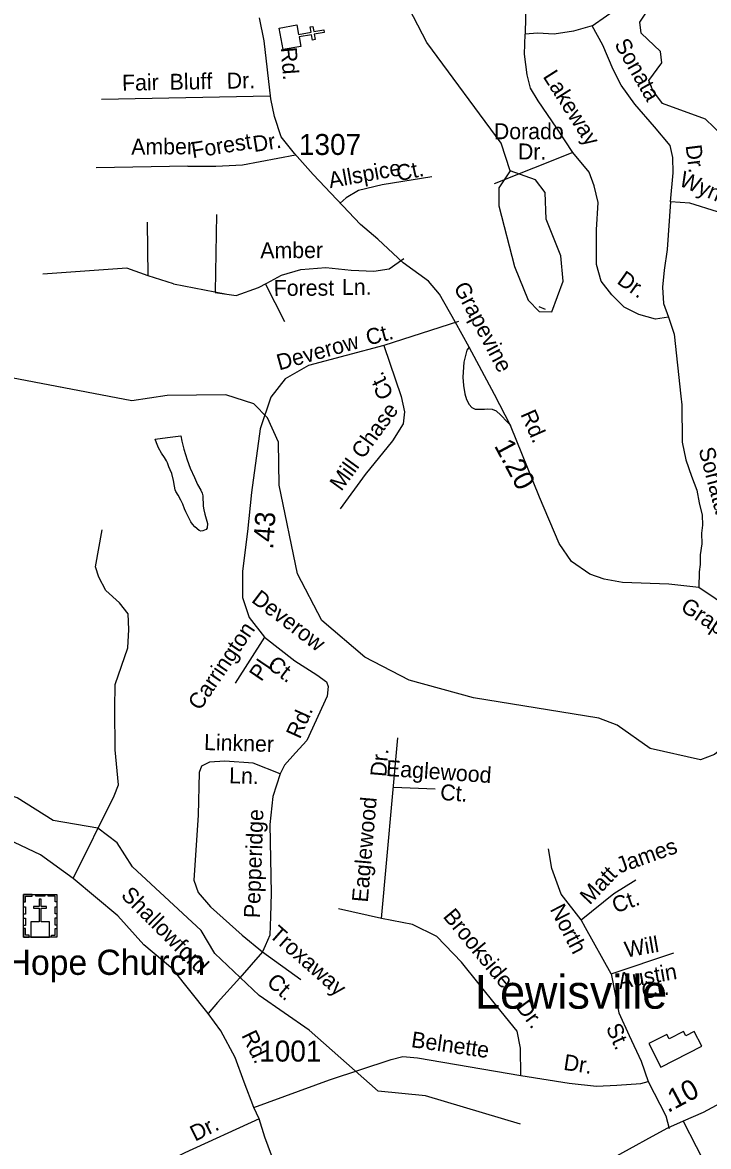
# Model space of a CAD drawing. Extents: x 1547597 to 1699558, y 810033 to 920809.
# Drawn here: x 1576329 to 1580417, y 856928 to 863625 of the extents above; entities that cross this region are included whole.
import ezdxf

# ---------------------------------------------------------------- set-up
doc = ezdxf.new("R2010")
doc.units = 0
for name, color, linetype in [('Exist Civil Demographics Community Label', 7, 'Continuous'), ('Exist Cultural Church CELL', 7, 'Continuous'), ('Exist Cultural Church with Cemetery CELL', 7, 'Continuous'), ('Exist Cultural Church with Cemetery Label', 7, 'Continuous'), ('Exist Cultural Warehouse Building Footprint', 7, 'Continuous'), ('Exist Hydrographic Creek Single Shore', 7, 'Continuous'), ('Exist Hydrographic Misc Water Feature', 7, 'Continuous'), ('Exist Hydrographic Pond Under 1500 Sq Ft', 7, 'Continuous'), ('Exist Road Non-System Type 51', 7, 'Continuous'), ('Exist Road Non-System Type 51 Label', 7, 'Continuous'), ('Exist Road Secondary Mileage Hundredths English Label', 7, 'Continuous'), ('Exist Road Secondary Type 51 Attributed', 7, 'Continuous'), ('Exist Road Secondary Type 51 Label', 7, 'Continuous'), ('Exist Road Secondary Type 51 Number Label', 7, 'Continuous')]:
    doc.layers.add(name, color=color, linetype=linetype)

msp = doc.modelspace()

# ---------------------------------------------------------------- linework, layer by layer
at = {"layer": 'Exist Cultural Church CELL'}
msp.add_lwpolyline([(1577964.1, 863610.7), (1577974.1, 863554.7), (1578049, 863567.9), (1578043.5, 863599.4), (1578059.2, 863602.2), (1578064.8, 863570.7), (1578124, 863581.1), (1578126.8, 863565.3), (1578067.6, 863554.9), (1578073.1, 863523.4), (1578057.4, 863520.6), (1578051.8, 863552.1), (1577976.8, 863538.9), (1577986.7, 863482.1), (1577881.9, 863463.6), (1577859.2, 863592.2)], close=True, dxfattribs=at)
at = {"layer": 'Exist Cultural Church with Cemetery CELL'}
for points in [[(1576335.3, 858430), (1576534.4, 858430), (1576534.4, 858175.3), (1576335.3, 858175.3)], [(1576335.3, 858386.6), (1576346.7, 858386.6), (1576346.7, 858418.8), (1576387.2, 858418.8), (1576387.2, 858430), (1576335.3, 858430)], [(1576378.4, 858175.4), (1576490.6, 858175.4), (1576490.6, 858265.9), (1576439.8, 858265.9), (1576439.8, 858347.4), (1576472.8, 858347.4), (1576472.8, 858358.4), (1576439.8, 858358.4), (1576439.8, 858400.7), (1576428.2, 858400.7), (1576428.2, 858358.4), (1576395.1, 858358.4), (1576395.1, 858347.4), (1576428.2, 858347.4), (1576428.2, 858265.9), (1576378.4, 858265.9)], [(1576409.4, 858429.9), (1576461.2, 858429.9), (1576461.2, 858418.5), (1576409.4, 858418.5)], [(1576534.5, 858386.6), (1576523.1, 858386.6), (1576523.1, 858418.8), (1576482.6, 858418.8), (1576482.6, 858429.9), (1576534.5, 858429.9)], [(1576335.3, 858312.5), (1576335.3, 858355.8), (1576346.7, 858355.8), (1576346.7, 858312.5)], [(1576523.1, 858313.5), (1576523.1, 858356.8), (1576534.5, 858356.8), (1576534.5, 858313.5)], [(1576335.3, 858245.3), (1576335.3, 858288.6), (1576346.7, 858288.6), (1576346.7, 858245.3)], [(1576523, 858247.6), (1576523, 858290.9), (1576534.4, 858290.9), (1576534.4, 858247.6)], [(1576368.4, 858175.4), (1576368.4, 858186.9), (1576346.4, 858186.9), (1576346.4, 858227.3), (1576335.3, 858227.3), (1576335.3, 858175.4)], [(1576501.3, 858175.3), (1576501.3, 858186.8), (1576523.3, 858186.8), (1576523.3, 858227.2), (1576534.4, 858227.2), (1576534.4, 858175.3)]]:
    msp.add_lwpolyline(points, close=True, dxfattribs=at)
at = {"layer": 'Exist Cultural Warehouse Building Footprint'}
msp.add_lwpolyline([(1580131.6, 857401.5), (1580375.9, 857525.1), (1580331.5, 857612.8), (1580280.5, 857586.9), (1580267.7, 857612.4), (1580182.3, 857569.2), (1580169.1, 857595.4), (1580061.2, 857540.7)], close=True, dxfattribs=at)
at = {"layer": 'Exist Hydrographic Creek Single Shore'}
msp.add_lwpolyline([(1579235.5, 862740.9), (1579180.5, 862906), (1578738.5, 863505.9), (1578446.5, 864069.9), (1578303.5, 864529.1), (1578280.5, 864720), (1578145.5, 865139.7), (1578072.5, 865282.3), (1578064.5, 865351.4), (1577879.5, 865795), (1577773.5, 865977.7), (1577495.5, 866301.8), (1577407.4, 866602.3), (1577350.4, 866679), (1577351.5, 866744.6)], dxfattribs=at)
at = {"layer": 'Exist Hydrographic Misc Water Feature'}
for points in [[(1580813.6, 859406.4), (1580663.5, 859393), (1580562.5, 859352.4), (1580452.5, 859262.7), (1580368.5, 859231.5), (1580069.5, 859299.9), (1579871.6, 859438.5), (1579763.5, 859480.1), (1579015.5, 859600.4), (1578633.4, 859706.6), (1578368.5, 859843.3), (1578113.5, 860061.8), (1577967.5, 860340.5), (1577858.5, 860868), (1577853.5, 861124.1), (1577789.5, 861269.9), (1577706.5, 861353.7), (1577540.5, 861406.3), (1577190.5, 861403.5), (1576981.4, 861371.6), (1576125.5, 861533.4), (1575884.5, 861613.8), (1575662.4, 861831.8)], [(1577271.7, 861161.6), (1577277.8, 861129.9), (1577291.2, 861082), (1577311, 861019.8), (1577328.5, 860970.2), (1577353.5, 860913.8), (1577372, 860873.3), (1577391.4, 860838.8), (1577400.4, 860821.1), (1577404.3, 860805.2), (1577405.7, 860744.2), (1577408.7, 860721.5), (1577414.9, 860695.6), (1577427.5, 860654.3), (1577430.6, 860639.3), (1577430.2, 860613.3), (1577424.2, 860604.3), (1577404, 860595.5), (1577391.4, 860594.1), (1577382.3, 860598.4), (1577356.8, 860620.5), (1577342, 860635.9), (1577332.2, 860650.2), (1577318.6, 860678), (1577301.5, 860709.3), (1577295.2, 860727.8), (1577284.7, 860754.6), (1577272.6, 860779.9), (1577256.4, 860808.6), (1577243.4, 860829.8), (1577239.4, 860839.8), (1577234.8, 860861.7), (1577229.6, 860896), (1577218.6, 860937.9), (1577208.8, 860959.9), (1577200.9, 860977.5), (1577193, 861001.9), (1577187.2, 861012.9), (1577175.9, 861033.1), (1577158, 861059.3), (1577140.2, 861090.6), (1577127.3, 861120.8), (1577120.2, 861142.7), (1577193.8, 861152.2), (1577271.7, 861161.6)], [(1579295.5, 857060.4), (1578730.5, 857229.4), (1578447.5, 857258.1), (1578036.5, 857621), (1577738.5, 857827.2), (1577475.5, 858078.8), (1577394.5, 858215.1), (1576983.5, 858594.3), (1576893.5, 858737.4), (1576778.4, 858825), (1576511.5, 858869.8), (1576297.5, 859005.5), (1576164.5, 859050.8), (1576082.5, 859167.4), (1576042.5, 859293), (1576046.5, 859558.8), (1576129.5, 860098.8), (1576126.5, 860433.7), (1576053.5, 860602.6), (1575971.5, 860669.9)]]:
    msp.add_lwpolyline(points, dxfattribs=at)
at = {"layer": 'Exist Hydrographic Pond Under 1500 Sq Ft'}
msp.add_line((1579445, 861916.1), (1579407.6, 861930.3), dxfattribs=at)
for points in [[(1580960.5, 862646.7), (1580860.5, 862642.2), (1580677.5, 862695.2), (1580545.6, 862819.3), (1580497.5, 862954.9), (1580399.5, 863048.7), (1580142.5, 863142.7), (1580085.5, 863219.2), (1580060.5, 863278.9), (1580137.5, 863385.6), (1580129.5, 863451.5), (1580014.5, 863562.2), (1580007.5, 863627.9), (1580101.5, 863770.4)], [(1579235.5, 862740.9), (1579167.5, 862640.4), (1579166.5, 862532.1), (1579260.5, 862172.3), (1579341.5, 861970.5), (1579407.5, 861903.5), (1579482.5, 861902), (1579551.5, 862084.4), (1579537.5, 862235.7), (1579448.5, 862454.2), (1579442.5, 862611.9), (1579385.5, 862688.6), (1579235.5, 862740.9)]]:
    msp.add_lwpolyline(points, dxfattribs=at)
at = {"layer": 'Exist Road Non-System Type 51'}
for p, q in [((1577805.1, 863186.8), (1576799.7, 863166.7)), ((1577639.8, 862777), (1577954.9, 862837.1)), ((1577313.7, 862769.6), (1576768.2, 862759.1)), ((1577313.7, 862769.6), (1577480.4, 862769.6)), ((1577480.4, 862769.6), (1577639.8, 862777)), ((1578472, 862658.4), (1578331.2, 862625)), ((1578768.5, 862706.6), (1578472, 862658.4)), ((1578331.2, 862625), (1578257.1, 862580.5)), ((1578257.1, 862580.5), (1578221.5, 862549.3)), ((1577484.1, 862480.4), (1577476.8, 862019.8)), ((1577077.8, 862116.7), (1577073.2, 862435.6)), ((1578514.3, 862157.8), (1578601.5, 862219.4)), ((1576950.3, 862162.2), (1576449.4, 862125.8)), ((1577077.8, 862116.7), (1576950.3, 862162.2)), ((1577784.3, 862072.5), (1577873.2, 862120.7)), ((1577873.2, 862120.7), (1577988.1, 862154)), ((1577988.1, 862154), (1578136.3, 862165.2)), ((1578136.3, 862165.2), (1578288.2, 862150.3)), ((1578288.2, 862150.3), (1578421.6, 862142.9)), ((1578421.6, 862142.9), (1578514.3, 862157.8)), ((1577228.4, 862068.8), (1577077.8, 862116.7)), ((1577228.4, 862068.8), (1577536.3, 862008.1)), ((1577736.1, 862046.5), (1577784.3, 862072.5)), ((1577891.7, 861842.6), (1577776.9, 862068.5)), ((1577476.7, 862016.8), (1577602.7, 861998.3)), ((1577602.7, 861998.3), (1577736.1, 862046.5)), ((1578467.7, 858286.1), (1578565.1, 859362)), ((1578787.6, 859056.6), (1578539.5, 859066.2)), ((1580265.5, 857078.7), (1580515, 856593.3))]:
    msp.add_line(p, q, dxfattribs=at)
for points in [[(1579356.4, 864184.1), (1579329.4, 863865.4), (1579323.3, 863556.4)], [(1579722.8, 863604.5), (1579894, 863724.7), (1580083.3, 863808.9), (1580194.4, 863863)], [(1579722.8, 863604.5), (1579611.7, 863574.4), (1579497.5, 863556.4), (1579398.4, 863562.4), (1579323.3, 863556.4)], [(1580190.9, 862557.3), (1580206.4, 862729.7), (1580203.4, 862819.9), (1580188.4, 862892.1), (1580095.3, 863003.3), (1579978.1, 863138.6), (1579897, 863252.8), (1579849, 863346), (1579785.9, 863490.3), (1579722.8, 863604.5)], [(1579608.4, 862851.4), (1579512.3, 862995.7), (1579401.2, 863158.1), (1579356.4, 863234.8), (1579335.3, 863312.9), (1579320.3, 863436.2), (1579323.3, 863556.4)], [(1579608.4, 862851.4), (1579140.1, 862663.6)], [(1580179.1, 861869.9), (1580101, 861857.9), (1580001.9, 861884.9), (1579914.8, 861930), (1579839.7, 862002.2), (1579776.6, 862083.3), (1579749.6, 862182.5), (1579749.6, 862390), (1579758.6, 862552.3), (1579734.6, 862653), (1579704.6, 862734.2), (1579608.4, 862851.4)], [(1580190.9, 862557.3), (1580170.1, 862272.7), (1580152.1, 862149.5), (1580143.1, 862047.3), (1580149.1, 861951.1), (1580179.1, 861869.9)], [(1580890.8, 862313.8), (1580800.6, 862367.9), (1580668.5, 862419), (1580470.2, 862497.2), (1580305, 862548.3), (1580190.9, 862557.3)], [(1580179.1, 861869.9), (1580212.1, 861767.7), (1580251.9, 861398.6), (1580257.4, 861346.6), (1580257.4, 861272.7), (1580260.2, 861204.3), (1580260.2, 861124.9), (1580281.9, 861019.8), (1580314.8, 860921.3), (1580347.6, 860839.2), (1580361.2, 860762.5), (1580378.1, 860689), (1580381.3, 860630.9), (1580374.9, 860581.9), (1580377.6, 860519), (1580366.7, 860453.3), (1580366.7, 860395.8), (1580361.2, 860352), (1580358.7, 860258.6)], [(1578927.2, 861843.7), (1578481.5, 861701.2)], [(1578481.5, 861701.2), (1578033.5, 861580.9), (1577893.9, 861503), (1577809.4, 861392.5), (1577744.5, 861204), (1577692.6, 860823.9), (1577669.8, 860593.2), (1577640.6, 860355.3), (1577640.6, 860199.3), (1577679.6, 860079.1), (1577770.5, 859962.1)], [(1578481.5, 861701.2), (1578585.1, 861396.1), (1578604.6, 861305.1), (1578598.1, 861233.6), (1578533.1, 861132.9), (1578370.8, 860931.4), (1578221.4, 860726.7)], [(1578990.2, 861690.5), (1578977.1, 861672.6), (1578958.2, 861600.8), (1578952.9, 861512.8), (1578956, 861462.7), (1578965.4, 861412.7), (1578974.9, 861378.5), (1578990.5, 861348.2), (1579006.2, 861332), (1579026, 861321.6), (1579048.2, 861321.4), (1579082, 861320.9), (1579102.1, 861322.7), (1579128.1, 861322.2), (1579152.1, 861311.9), (1579179.6, 861285.5), (1579217.2, 861244.9), (1579230.9, 861232.6), (1579237.3, 861224.9)], [(1576631.7, 858524.3), (1576875.2, 859018.2), (1576901.2, 859083.2), (1576881.7, 859291.1), (1576878.4, 859538.1), (1576881.7, 859681.1), (1576956.4, 859898.8), (1576962.8, 860007.6), (1576959.6, 860101.8), (1576907.6, 860166.8), (1576826.5, 860241.5), (1576784.3, 860319.5), (1576764.8, 860381.3), (1576803.7, 860602.2)], [(1577770.5, 859962.1), (1577595.2, 859689.2)], [(1577770.5, 859962.1), (1577952.3, 859822.4), (1578082.2, 859737.9), (1578140.6, 859695.7), (1578150.4, 859669.7), (1578143.9, 859611.2), (1578023.8, 859348), (1577956, 859274.3), (1577891, 859199.6), (1577865, 859148.3)], [(1577865, 859148.3), (1577703, 859211.2), (1577534.2, 859224.2), (1577443.3, 859217.7), (1577394.6, 859194.9), (1577381.6, 859155.9), (1577375.1, 858902.5), (1577349.1, 858515.8), (1577375.1, 858441.1), (1577449.8, 858356.6), (1577638.1, 858187.6), (1577758.2, 858086.9)], [(1577865, 859148.3), (1577819.9, 859013), (1577803.7, 858847.3), (1577810.1, 858437.8), (1577806.9, 858298.1), (1577803.7, 858187.6), (1577774.4, 858122.7), (1577758.2, 858086.9)], [(1579658.4, 858279.4), (1579538.3, 858432.2), (1579483.1, 858584.9), (1579463.6, 858701.9)], [(1579658.4, 858279.4), (1579853.2, 858435.4), (1579983.1, 858516.6)], [(1578467.7, 858286.1), (1578211.2, 858344.6)], [(1579298.7, 857351.4), (1579295.5, 857513.8), (1579276, 857614.6), (1579155.9, 857764), (1578944.8, 858027.2), (1578798.7, 858179.9), (1578652.8, 858250.3), (1578467.7, 858286.1)], [(1579836.9, 857956), (1579684.4, 858230.7), (1579658.4, 858279.4)], [(1577758.2, 858086.9), (1577624.5, 857932.5), (1577491.4, 857786.3), (1577435, 857720.7)], [(1577758.2, 858086.9), (1577988.1, 857922.7)], [(1579836.9, 857956), (1580210.4, 858081.2)], [(1579836.9, 857956), (1579882.4, 857725.3), (1579944.1, 857588.9), (1580015.5, 857436.1), (1580057.7, 857315.9)], [(1577707.7, 857159.9), (1578159.1, 857325.4), (1578526, 857445.6), (1578594.2, 857465.1), (1578681.8, 857455.3), (1579298.7, 857351.4)], [(1579298.7, 857351.4), (1579586.9, 857306.2), (1579749.3, 857286.7), (1579869.4, 857293.2), (1580012.3, 857302.9), (1580057.7, 857315.9)], [(1580057.7, 857315.9), (1580161.6, 857111.2), (1580182, 857034.5)], [(1577738.7, 857092.1), (1577295.8, 856889.7), (1576909.4, 856694.8), (1576611.2, 856527.4)]]:
    msp.add_lwpolyline(points, dxfattribs=at)
at = {"layer": 'Exist Road Secondary Type 51 Attributed'}
for points in [[(1580955.5, 859857.2), (1580358.7, 860258.6), (1580180.5, 860279.5), (1579904.5, 860289.1), (1579795.4, 860308.4), (1579708.8, 860337.3), (1579599.7, 860414.3), (1579525.9, 860520.3), (1579410.4, 860796.5), (1579237.3, 861224.9), (1579141, 861407.9), (1578990.2, 861690.5), (1578906.8, 861841.5), (1578814.6, 862006.6), (1578747.3, 862083.7), (1578596.5, 862192.8), (1578445.7, 862334.1), (1578343, 862420.8), (1578060.6, 862719.5), (1577949.5, 862843.8), (1577869.3, 862943.3), (1577830.8, 863065.4), (1577808.4, 863171.3), (1577769.9, 863516.9), (1577740.4, 863653.3)], [(1577839.2, 856806.3), (1577773.5, 856983.6), (1577738.7, 857092.1), (1577707.7, 857159.9), (1577649.6, 857311), (1577595.6, 857457.2), (1577510.5, 857616.1), (1577435, 857720.7), (1577224.2, 857985.1), (1577052, 858130.4), (1576897.2, 858302.8), (1576631.7, 858524.3), (1576437.1, 858666.3), (1576280.9, 858739.6), (1576073.8, 858832.6), (1575806.7, 858881), (1575666.1, 858894.2), (1575433.8, 858884.6), (1575222.9, 858849.7), (1574997.2, 858808.9), (1574629.5, 858723.7), (1574405, 858675.3)], [(1580661, 857279.2), (1580384.2, 857130.2), (1580265.5, 857078.7), (1580172.6, 857036.3), (1580080.4, 856987.7), (1579807.4, 856837), (1579681.7, 856779.9), (1579542.2, 856705.8), (1579438.7, 856638.1), (1579340, 856585.4), (1579277.3, 856557.6), (1579119.8, 856466.2), (1578923.9, 856398.8), (1578736.4, 856317.6), (1578668.2, 856288.3), (1578502.6, 856229.1), (1578279.3, 856149.5), (1578203.1, 856124.1)]]:
    msp.add_lwpolyline(points, dxfattribs=at)

# ---------------------------------------------------------------- texts
at = {"layer": 'Exist Civil Demographics Community Label'}
msp.add_text('Lewisville', height=200, dxfattribs=at).set_placement((1579025.8, 857749))
at = {"layer": 'Exist Cultural Church with Cemetery Label'}
msp.add_text('New Hope Church', height=150, dxfattribs=at).set_placement((1575777.7, 857950.4))
at = {"layer": 'Exist Road Non-System Type 51 Label'}
for s, rotation, p in [('Sonata', 299.67736, (1579852.8, 863496.7)), ('Bluff', 1.14611, (1577206.3, 863224)), ('Dr.', 1.14611, (1577546.6, 863230.8)), ('Lakeway', 302.35218, (1579426.6, 863303.5)), ('Fair', 1.14611, (1576922.9, 863218.4)), ('Dorado', 0.06339, (1579137.5, 862929.7)), ('Amber', 0.3618, (1576977, 862837.9)), ('Forest', 9.06732, (1577343, 862816.4)), ('Dr.', 9.06732, (1577709.1, 862853)), ('Dr.', 359.66326, (1579280.7, 862809.5)), ('Dr.', 277.11257, (1580279.8, 862892)), ('Allspice', 10.31962, (1578161.2, 862637.7)), ('Ct.', 12.07278, (1578567.9, 862678.1)), ('Wyntfield', 336.80526, (1580234.4, 862656.2)), ('Amber', 0.30021, (1577745.9, 862220.1)), ('Dr.', 324.84915, (1579865.2, 862074.4)), ('Forest', 0.30021, (1577826.2, 861996)), ('Ln.', 0.30021, (1578232.5, 862001.8)), ('Ct.', 15.17136, (1578389.4, 861699.4)), ('Deverow', 15.54577, (1577858.5, 861551.8)), ('Ct.', 116.03185, (1578542.9, 861407.3)), ('Chase', 53.99701, (1578357.8, 861019)), ('Sonata', 284.8955, (1580356.3, 861081.5)), ('Mill', 53.99701, (1578228.8, 860827.8)), ('Deverow', 322.67658, (1577687.8, 860176)), ('Carrington', 55.91496, (1577386.5, 859520.4)), ('Ct.', 322.67658, (1577781.3, 859784.1)), ('Pl.', 55.91496, (1577751.8, 859693.8)), ('Rd.', 65.91457, (1577982.2, 859351.3)), ('Linkner', 358.33999, (1577409.8, 859290.4)), ('Dr.', 85.05526, (1578495.6, 859127.9)), ('Ln.', 358.33999, (1577559.3, 859092.5)), ('Eaglewood', 356.09673, (1578493, 859136)), ('Ct.', 356.09673, (1578815.5, 858993)), ('Eaglewood', 85.05526, (1578386.1, 858380.2)), ('Pepperidge', 88.0534, (1577742.8, 858287.4)), ('James', 19.65247, (1579886.6, 858554.3)), ('Matt', 46.76793, (1579709.3, 858363.3)), ('Ct.', 19.35867, (1579861.8, 858316.7)), ('North', 297.24631, (1579469.6, 858342.5)), ('Brookside', 309.61719, (1578830.2, 858296.9)), ('Troxaway', 318.59965, (1577792.9, 858181.9)), ('Will', 9.97244, (1579925.2, 858053.2)), ('Austin', 9.97244, (1579886.2, 857865.8)), ('Ct.', 318.59965, (1577777.7, 857897.8)), ('Ct.', 9.97244, (1580026.2, 857806)), ('Dr.', 306.43739, (1579266.4, 857757.7)), ('St.', 294.21109, (1579803.1, 857636.3)), ('Belnette', 351.85238, (1578641.1, 857520.4)), ('Dr.', 351.31761, (1579548.5, 857385.4)), ('Dr.', 26.56716, (1577357.4, 856956.1))]:
    msp.add_text(s, height=95, rotation=rotation, dxfattribs=at).set_placement(p)
at = {"layer": 'Exist Road Secondary Mileage Hundredths English Label'}
for s, rotation, p in [('1.20', 298.05143, (1579136.9, 861103.9)), ('.43', 86.07256, (1577821.9, 860483.6)), ('.10', 28.11835, (1580174.3, 857126.7))]:
    msp.add_text(s, height=120, rotation=rotation, dxfattribs=at).set_placement(p)
at = {"layer": 'Exist Road Secondary Type 51 Label'}
for s, rotation, p in [('Rd.', 274.2126, (1577867.9, 863475.2)), ('Grapevine', 297.8373, (1578895.1, 862048.6)), ('Rd.', 293.78999, (1579294.5, 861291.6)), ('Grapevine', 326.73844, (1580243.8, 860125.4)), ('Shallowford', 315.04472, (1576910.6, 858419.1)), ('Rd.', 295.76933, (1577631.9, 857591.1))]:
    msp.add_text(s, height=95, rotation=rotation, dxfattribs=at).set_placement(p)
at = {"layer": 'Exist Road Secondary Type 51 Number Label'}
for s, p in [('1307', (1577975.5, 862835.9)), ('1001', (1577738.9, 857433.9))]:
    msp.add_text(s, height=125, dxfattribs=at).set_placement(p)

doc.saveas('drawing.dxf')
